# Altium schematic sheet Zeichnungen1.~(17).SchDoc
size A4; PageSetup: Record=PageOptions¦CenterHorizontal=True¦CenterVertical=True¦PrintScale=1.00¦XCorrection=1.00¦YCorrection=1.00¦PrintKind=0¦BorderSize=5000000¦LeftOffset=0¦BottomOffset=0¦Orientation=2¦PaperLength=1000¦PaperWidth=1000¦Scale=100¦PaperSource=7¦PrintQuality=-3¦MediaType=1¦DitherType=10¦PrintScaleMode=1¦PaperKind=A4¦PaperIndex=9
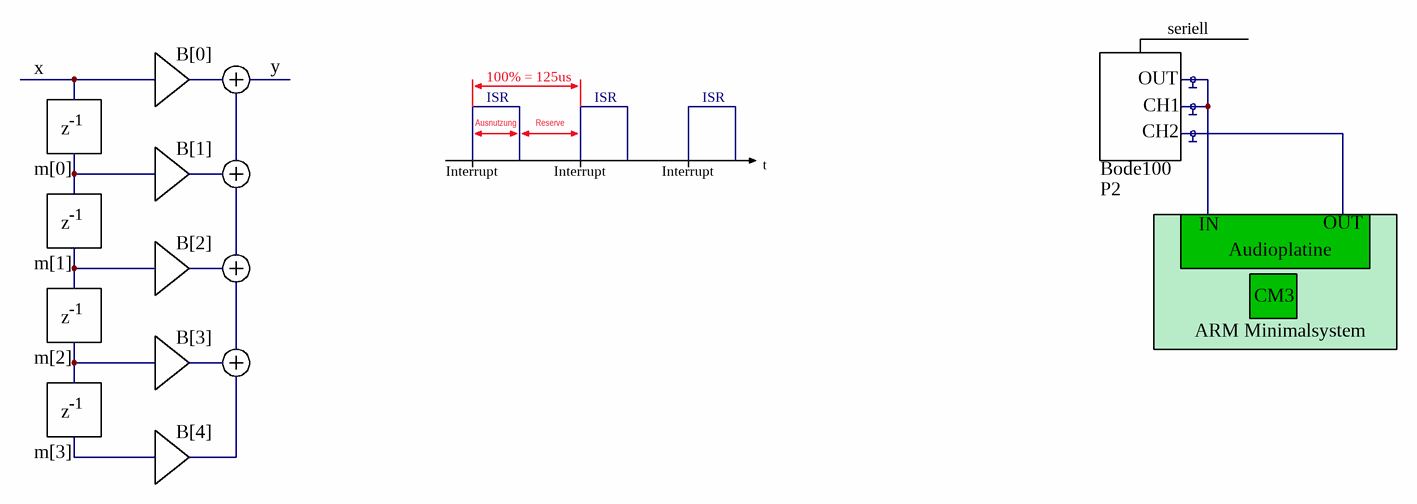
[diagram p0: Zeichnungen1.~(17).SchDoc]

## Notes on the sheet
- x
- B[0]
- y
- 100% = 125us
- seriell
- z
- -1
- Ausnutzung
- ISR
- Reserve
- OUT
- CH2
- CH1
- m[0]
- B[1]
- Interrupt
- t
- Bode100
- P2
- m[1]
- B[2]
- IN
- Audioplatine
- B[3]
- ARM Minimalsystem
- CM3
- m[2]
- m[3]
- B[4]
